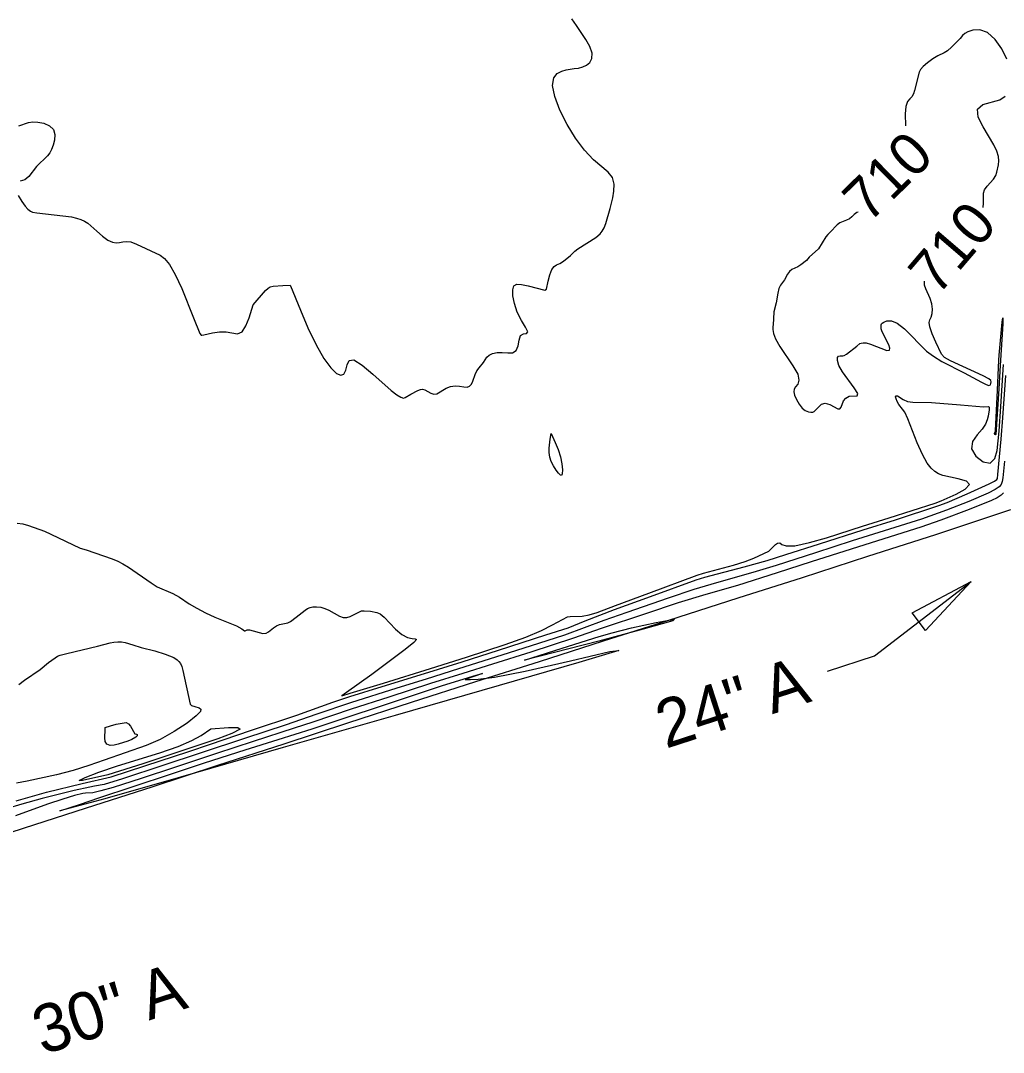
# Model space of a CAD drawing. Extents: x -468541894 to 3393103, y -306086142 to 1227927.
# Drawn here: x 1845028 to 1845797, y 538378 to 539185 of the extents above; entities that cross this region are included whole.
import ezdxf

# ---------------------------------------------------------------- set-up
doc = ezdxf.new("R2010")
doc.units = 0
for name, color, linetype in [('DT_X_Contour_Minor', 7, 'Continuous'), ('Level 14', 7, 'Continuous'), ('Level 19', 7, 'Continuous'), ('Level 40', 7, 'Continuous')]:
    doc.layers.add(name, color=color, linetype=linetype)

msp = doc.modelspace()

# ---------------------------------------------------------------- linework, layer by layer
at = {"layer": 'DT_X_Contour_Minor'}
for points in [[(1845461.01, 539147.19), (1845464.33, 539147.67), (1845467.64, 539148.5), (1845470.72, 539149.91), (1845473.29, 539152.12), (1845474.88, 539155.24), (1845474.95, 539159.36), (1845473.17, 539164.47), (1845470.1, 539170.1), (1845462.86, 539180.84), (1845459.23, 539186.18)], [(1845799.27, 539154.71), (1845795.43, 539162.73), (1845790.16, 539170.1), (1845784.17, 539175.34), (1845778.14, 539177.45), (1845772.75, 539177.26), (1845768.67, 539176.01), (1845766.27, 539174.69), (1845764.7, 539173.11), (1845762.8, 539170.81), (1845759.74, 539167.56), (1845756.08, 539164.04), (1845752.72, 539161.16), (1845750.24, 539159.55), (1845745.32, 539157.19), (1845741.46, 539154.78), (1845737.24, 539151.76), (1845733.72, 539148.84), (1845731.69, 539146.51), (1845730.76, 539144.48), (1845727.11, 539130.02), (1845726.27, 539127.39), (1845725.09, 539125.28), (1845723.41, 539123.59), (1845721.65, 539121.42), (1845720.32, 539117.68), (1845719.8, 539111.75), (1845720.04, 539102.53)], [(1845238.97, 538977.85), (1845239.1, 538977.53), (1845246.91, 538958.27), (1845252.79, 538944.59), (1845259.15, 538931.22), (1845265.21, 538920.66), (1845270.62, 538913.3), (1845275.12, 538908.97), (1845278.55, 538907.49), (1845280.95, 538908.45), (1845282.46, 538911.4), (1845283.4, 538915.59), (1845284.99, 538919.04), (1845288.66, 538919.43), (1845295.26, 538915.27), (1845303.51, 538908.31), (1845317.86, 538895.6), (1845322.41, 538892.1), (1845325.49, 538890.24), (1845327.46, 538889.71), (1845328.97, 538890.18), (1845333.22, 538892.8), (1845338.75, 538895.63), (1845340.79, 538896.44), (1845342.49, 538896.63), (1845344.29, 538896.09), (1845348.99, 538893.47), (1845351.38, 538892.68), (1845353.51, 538893), (1845361.01, 538897.38), (1845364.42, 538898.64), (1845367.99, 538899.24), (1845371.45, 538899.01), (1845374.59, 538898.47), (1845377.23, 538898.3), (1845379.21, 538899.03), (1845380.66, 538900.61), (1845381.75, 538902.81), (1845383.68, 538908.2), (1845384.94, 538910.88), (1845386.6, 538913.25), (1845390.06, 538917.49), (1845392.63, 538921.56), (1845394.44, 538923.25), (1845397.15, 538924.5), (1845400.66, 538925.22), (1845404.71, 538925.35), (1845408.99, 538925.04), (1845412.88, 538925.15), (1845415.73, 538926.75), (1845417.14, 538930.46), (1845417.9, 538934.95), (1845419.1, 538938.45), (1845421.41, 538939.78), (1845423.75, 538940.17), (1845424.62, 538941.44), (1845423, 538945), (1845419.83, 538950.42), (1845416.53, 538956.87), (1845414.25, 538963.52), (1845413.13, 538969.6), (1845413.03, 538974.4), (1845413.92, 538977.36), (1845416.04, 538978.63), (1845419.73, 538978.57), (1845425.03, 538977.53), (1845438.13, 538974.09), (1845439.27, 538974.68), (1845440.77, 538981.16), (1845442.02, 538986.08), (1845443.54, 538990.24), (1845445.27, 538992.58), (1845447.28, 538993.75), (1845449.7, 538994.82), (1845452.55, 538996.59), (1845458, 539001.09), (1845461.6, 539004.62), (1845463.82, 539006.3), (1845477.97, 539015.13), (1845481.19, 539018.11), (1845482.89, 539020.08), (1845484.47, 539022.7), (1845485.81, 539026.1), (1845489.05, 539037.74), (1845491.13, 539046.08), (1845492.06, 539051.34), (1845492.23, 539056.88), (1845490.89, 539061.98), (1845487.5, 539066.21), (1845476.06, 539075.95), (1845469.1, 539083.53), (1845462.03, 539092.94), (1845455.4, 539103.6), (1845449.76, 539114.81), (1845445.77, 539125.39), (1845444.06, 539134.07), (1845445.02, 539139.9), (1845447.81, 539143.35), (1845451.33, 539145.23), (1845454.68, 539146.26), (1845461.01, 539147.19)], [(1845780.63, 539038.55), (1845781, 539042.01), (1845781.06, 539049.74), (1845781.83, 539052.58), (1845783.83, 539055.35), (1845788.92, 539060.89), (1845790.52, 539063.64), (1845791.44, 539066.39), (1845792.67, 539072.01), (1845792.99, 539075.1), (1845792.66, 539078.58), (1845791.37, 539082.67), (1845788.95, 539087.7), (1845780.63, 539101.66), (1845776.9, 539109.37), (1845776.35, 539115.55), (1845780.41, 539119.13), (1845793.71, 539122.88), (1845797.96, 539125.72)], [(1845026.88, 539102.59), (1845034.31, 539105.12), (1845037.76, 539105.65), (1845041.66, 539105.48), (1845046.25, 539104.46), (1845050.68, 539102.5), (1845053.86, 539099.53), (1845055.02, 539095.62), (1845054.64, 539091.32), (1845053.55, 539087.31), (1845052.39, 539084.09), (1845051.04, 539081.49), (1845049.2, 539079.16), (1845040.57, 539070.72), (1845034.61, 539062.95), (1845031.38, 539060.23), (1845027.86, 539059.15)], [(1845026.32, 539048.13), (1845029.14, 539043.26), (1845031.73, 539039.64), (1845033.96, 539037.27), (1845035.88, 539035.86), (1845037.56, 539035.11), (1845040.98, 539034.58), (1845067.94, 539031.34), (1845071.98, 539030.37), (1845075.38, 539029.27), (1845078.17, 539028.01), (1845080.81, 539026.28), (1845087.84, 539020.14), (1845092.22, 539016.32), (1845096.43, 539013.19), (1845099.99, 539011.48), (1845102.98, 539010.97), (1845105.61, 539011.23), (1845108.12, 539011.8), (1845110.9, 539012.13), (1845114.37, 539011.67), (1845118.76, 539010.08), (1845137.3, 539001.43), (1845140.6, 538998.73), (1845144.48, 538994.03), (1845149.03, 538986.31), (1845154.19, 538975.23), (1845163.4, 538952.51)], [(1845683.02, 539035.08), (1845682.08, 539034.75), (1845679.94, 539033.16), (1845678.15, 539031.33), (1845676.22, 539029.74), (1845673.82, 539028.67), (1845671.16, 539027.82), (1845668.63, 539026.73), (1845666.48, 539025.06), (1845661.06, 539019.32), (1845659.28, 539017.65), (1845657.64, 539015.7), (1845651.92, 539006.3), (1845644.82, 538999.69), (1845642.55, 538997.24)], [(1845642.55, 538997.24), (1845638.1, 538993.77), (1845635.84, 538992.38), (1845631.2, 538990.07), (1845629.26, 538988.6), (1845627.79, 538986.57), (1845625.34, 538982), (1845622.39, 538978.03), (1845621.1, 538975.37), (1845620.18, 538971.75), (1845618.89, 538964.1), (1845616.95, 538957.04), (1845616.78, 538951.56), (1845616.52, 538947.15), (1845616.29, 538945.43), (1845616.3, 538943.31), (1845616.87, 538940.25), (1845618.48, 538935.92), (1845621.71, 538930.08), (1845631.99, 538914.97), (1845635.77, 538908.25), (1845636.73, 538903.6), (1845635.71, 538900.61), (1845634.1, 538898.52), (1845633.04, 538896.63), (1845632.79, 538894.52), (1845633.36, 538891.85), (1845634.75, 538888.43), (1845636.76, 538884.83), (1845639.14, 538881.78), (1845641.66, 538879.84), (1845644.06, 538878.85), (1845646.06, 538878.51), (1845647.52, 538878.57), (1845648.72, 538879.18), (1845654.24, 538884.84), (1845657.23, 538885.73), (1845660.74, 538884.72), (1845667.07, 538881.27), (1845668.76, 538881.29), (1845669.7, 538882.65), (1845671.6, 538887.41), (1845673.35, 538889.69), (1845675.96, 538891.06), (1845682.14, 538891.43), (1845682.7, 538893.25), (1845679.97, 538897.74), (1845670.81, 538910.13), (1845667.99, 538915.21), (1845666.81, 538918.9), (1845666.84, 538921.25), (1845667.64, 538922.39), (1845668.82, 538922.7), (1845671.03, 538922.61), (1845672.16, 538922.98), (1845673.88, 538924.05), (1845681.88, 538930.34), (1845684.42, 538932.27), (1845685.41, 538932.63), (1845686.92, 538932.88), (1845689.26, 538932.75), (1845692.66, 538931.86), (1845705.51, 538926.8), (1845707.46, 538927.06), (1845707.8, 538928.69), (1845706.94, 538931.35), (1845701.86, 538941.37), (1845701.04, 538943.86), (1845700.92, 538946.9), (1845701.15, 538947.69), (1845701.76, 538948.31), (1845703.11, 538949.05), (1845705.49, 538949.96), (1845708.97, 538950.09), (1845713.54, 538948.25), (1845719.1, 538943.71), (1845736.32, 538926.44), (1845741.83, 538922.3), (1845748.51, 538918.26), (1845765.86, 538909.29), (1845779.48, 538902.16), (1845783.11, 538900.19), (1845785.23, 538899.45), (1845786.35, 538899.92), (1845786.83, 538901.11), (1845786.95, 538902.42), (1845786.74, 538903.46), (1845785.1, 538904.75), (1845780.62, 538907.01), (1845755.08, 538918.77), (1845750.39, 538921.49), (1845748.05, 538924.02), (1845743.72, 538933.34), (1845740.95, 538939.77), (1845738.96, 538945.3), (1845738.49, 538948.76), (1845739.11, 538950.86), (1845740.13, 538952.84), (1845740.94, 538955.65), (1845741.2, 538959.25), (1845740.67, 538963.32)], [(1845740.67, 538963.32), (1845739.25, 538967.55), (1845735.84, 538975.18), (1845734.99, 538977.98), (1845734.85, 538981.04)], [(1845163.4, 538952.51), (1845168.42, 538940.03), (1845169.41, 538938.85), (1845169.98, 538938.71), (1845171.51, 538939.01), (1845178.25, 538940.58), (1845183.58, 538941.41), (1845189.03, 538941.48), (1845197.88, 538939.93), (1845201.39, 538941.43), (1845204.41, 538946.1), (1845206.87, 538952.35), (1845209.98, 538962.44), (1845219.76, 538973.8), (1845221.65, 538975.69), (1845223.36, 538976.65), (1845225.71, 538977.12), (1845233.13, 538977.62), (1845238.97, 538977.85)], [(1845790.42, 538864.02), (1845792.04, 538895.92), (1845793.02, 538919.23), (1845793.22, 538923.21), (1845795.69, 538948.97), (1845796.19, 538952.47), (1845796.06, 538947.59), (1845794.09, 538915.06), (1845792.95, 538896.87), (1845790.61, 538861.15), (1845790.41, 538860.94), (1845789.78, 538861.25), (1845789.66, 538861.93), (1845790.35, 538863.31), (1845790.42, 538864.02)], [(1845312.41, 538718.33), (1845321.34, 538708.99), (1845326.17, 538704.83), (1845330.6, 538702.58), (1845334.24, 538701.76), (1845336.78, 538701.49), (1845337.65, 538700.81), (1845335.5, 538698.45), (1845328.77, 538693.06), (1845302.68, 538673.56), (1845282.99, 538659.36), (1845279.46, 538656.85), (1845285.72, 538658.87), (1845311.81, 538666.89), (1845348.58, 538678.19), (1845376.75, 538687.01), (1845407.1, 538697), (1845423.11, 538702.82), (1845435.47, 538708.05), (1845444.14, 538712.32), (1845455.8, 538718.55), (1845457.87, 538718.94), (1845467.29, 538719.24), (1845472.64, 538720.19), (1845478.83, 538722.03), (1845493.31, 538727.61), (1845519.35, 538737.21), (1845557.19, 538751.1), (1845562.02, 538752.67), (1845585.44, 538759.05), (1845594.67, 538761.9), (1845601.35, 538764.42), (1845613.23, 538770.06), (1845618.26, 538775.22), (1845620.03, 538776.32), (1845621.72, 538776.44), (1845623.42, 538775.3), (1845626.71, 538774.05), (1845633.55, 538774.17), (1845644.94, 538776.65), (1845658.17, 538780.46), (1845686.37, 538789.41), (1845707.18, 538796), (1845743.08, 538807.48), (1845747.78, 538809.21), (1845759.7, 538814.55), (1845766.71, 538818.45), (1845770.15, 538822.08), (1845767.65, 538824.75), (1845761.31, 538826.59), (1845749.23, 538829.15), (1845745.76, 538830.49), (1845742.97, 538832.24), (1845740.07, 538834.78), (1845736.83, 538838.89), (1845733.18, 538845.45), (1845729.16, 538854.78), (1845721.8, 538873.48), (1845719.37, 538878.55), (1845717.65, 538881.09), (1845714.8, 538884.68), (1845713.51, 538886.93), (1845712.59, 538889.04), (1845712.27, 538890.64), (1845712.61, 538891.48), (1845713.67, 538891.32), (1845718.08, 538888.43), (1845721.49, 538887.04), (1845725.87, 538886.47), (1845740.32, 538886.12), (1845763.1, 538884.3), (1845781.02, 538882.8), (1845784.94, 538883.07), (1845785.32, 538882.51), (1845785.31, 538880.49), (1845784.56, 538875.4), (1845783.89, 538872.66), (1845782.5, 538869.31), (1845779.88, 538865.36), (1845775.96, 538860.83), (1845772.51, 538855.74), (1845771.73, 538850.07), (1845775.04, 538844.16), (1845780.74, 538839.69), (1845786.33, 538838.7), (1845789.88, 538842.38), (1845791.62, 538848.77), (1845793.16, 538863.81), (1845794.45, 538883.1), (1845796.73, 538915.99)], [(1845076.24, 538588.26), (1845099.08, 538593.58), (1845125.21, 538602.12), (1845159.65, 538613.44), (1845176.72, 538619.15), (1845207.86, 538629.66), (1845244.15, 538641.88), (1845272.35, 538651.81), (1845285.71, 538656.32), (1845310.94, 538664.15), (1845343.94, 538674.33), (1845373.34, 538683.56), (1845401.9, 538692.64), (1845438.92, 538704.46), (1845456.21, 538710.14), (1845469.59, 538715.39), (1845492.61, 538724.46), (1845520.65, 538734.57), (1845556.38, 538747.45), (1845563.02, 538749.52), (1845593.8, 538757.76), (1845611.97, 538762.71), (1845626.46, 538767.24), (1845652.67, 538775.65), (1845686.83, 538786.57), (1845712.15, 538794.56), (1845746.15, 538805.64), (1845752.55, 538808.06), (1845768.17, 538814.8), (1845785.32, 538822.59), (1845789.71, 538824.77), (1845791.47, 538825.93), (1845791.88, 538826.71), (1845792.29, 538829.88), (1845794.74, 538857.57), (1845796.22, 538874.31), (1845798.48, 538907.39)], [(1845442.9, 538862.08), (1845446.19, 538854.81), (1845448.36, 538849.45), (1845450.26, 538843.66), (1845451.39, 538838.22), (1845451.8, 538833.68), (1845451.67, 538830.54), (1845451.14, 538829.16), (1845450.19, 538829.37), (1845448.76, 538830.89), (1845446.86, 538833.41), (1845444.84, 538836.59), (1845443.12, 538840.06), (1845442.03, 538843.54), (1845441.52, 538847.02), (1845441.48, 538850.6), (1845442.19, 538857.59), (1845442.9, 538862.08)], [(1845797.49, 538840.44), (1845796.14, 538827.41), (1845795.61, 538824.41), (1845794.84, 538822.16), (1845793.22, 538820.23), (1845790, 538818.11), (1845784.67, 538815.39), (1845769.65, 538808.78), (1845752.19, 538801.91), (1845732.43, 538795.02), (1845703.25, 538785.75), (1845678.36, 538777.92), (1845649.53, 538768.66), (1845618.91, 538758.8), (1845600.75, 538753.2), (1845572.26, 538745.32), (1845554.57, 538740.11), (1845534.46, 538733.28), (1845502.05, 538721.91), (1845484.15, 538715.79), (1845453.31, 538704.36), (1845433.04, 538697.76), (1845404.48, 538688.65), (1845370.64, 538678.03), (1845345.21, 538669.96), (1845322.28, 538662.75), (1845286.19, 538651.39), (1845259.9, 538642.46), (1845234.99, 538634.03), (1845204.01, 538623.9)], [(1845796.73, 538815.7), (1845794.68, 538813.63), (1845791.76, 538811.76), (1845787.17, 538809.6), (1845769.77, 538802.63), (1845747.52, 538794.16), (1845732.05, 538788.79), (1845702.96, 538779.72), (1845677.41, 538771.66), (1845646.38, 538761.67), (1845619.57, 538752.99), (1845588.71, 538743.26), (1845563.8, 538736.08), (1845542.41, 538729.54), (1845516.66, 538720.89), (1845482, 538709.5), (1845460.4, 538701.91), (1845427.15, 538691.07), (1845397.07, 538681.54), (1845374.06, 538674.44), (1845348.65, 538666.41), (1845316.09, 538655.95), (1845286.67, 538646.45), (1845256.54, 538636.32), (1845242.18, 538631.54), (1845209.89, 538621.3), (1845181.37, 538611.88), (1845148.39, 538600.95), (1845122.34, 538592.37), (1845100.49, 538585.32), (1845091.01, 538582.56), (1845084.65, 538581.13), (1845078.93, 538580.69), (1845076.77, 538580.56), (1845070.44, 538578.91), (1845061.34, 538576.2), (1845049.11, 538572.12), (1845024.3, 538563.14)], [(1845025.45, 538791.79), (1845029.95, 538791.37), (1845034.32, 538790.14), (1845046.91, 538785.52), (1845051.91, 538783.35), (1845074.71, 538772.39), (1845079.33, 538770.96), (1845099.87, 538763.86), (1845104.25, 538762.09), (1845108.08, 538760.14), (1845112.61, 538757.34), (1845130.18, 538745.31), (1845135, 538742.15), (1845147.22, 538736.9), (1845152.37, 538733.94), (1845160.09, 538728.87), (1845165.96, 538725.35), (1845172.78, 538721.74), (1845180.12, 538718.45), (1845196.99, 538711.54), (1845201.06, 538709.18), (1845203.19, 538707.73), (1845203.86, 538707.6), (1845205.28, 538708.42), (1845207.14, 538708.38), (1845217.61, 538705.62), (1845220.1, 538705.92), (1845221.92, 538707.03), (1845225.8, 538710.13), (1845228.21, 538711.52), (1845230.65, 538712.52), (1845237.18, 538713.88), (1845239.26, 538714.98), (1845243.63, 538718.4), (1845250.56, 538723.84), (1845252.5, 538725.11), (1845254.45, 538725.99), (1845256.76, 538726.47), (1845259.65, 538726.53), (1845262.9, 538726.15), (1845266.17, 538725.26), (1845269.21, 538723.86), (1845277.6, 538719.11), (1845280.41, 538718.24), (1845283.2, 538718.14), (1845285.94, 538718.95), (1845294.66, 538723.2), (1845296.69, 538723.4), (1845301.66, 538722.97), (1845306.61, 538722.08), (1845309.19, 538720.91), (1845312.41, 538718.33)], [(1845422.22, 538684.68), (1845451.49, 538694.08), (1845480.42, 538703.34), (1845490.69, 538706.21), (1845505.87, 538709.94), (1845524.99, 538714.11), (1845539.3, 538716.74), (1845538.13, 538715.47), (1845514.99, 538708.93), (1845480.15, 538699.71), (1845422.22, 538684.68)], [(1845026.75, 538665.74), (1845031.17, 538669.11), (1845043.6, 538677.38), (1845049.99, 538682.87), (1845055.11, 538686.61), (1845057.11, 538687.77), (1845059, 538688.56), (1845064.26, 538689.96), (1845088.32, 538695.65), (1845098.19, 538698.41), (1845101.18, 538698.9), (1845104.2, 538699.12), (1845107.07, 538698.97), (1845109.87, 538698.46), (1845115.91, 538696.66), (1845122.54, 538694.59), (1845133.06, 538692.11), (1845141.09, 538689.44), (1845148.01, 538686.72), (1845150.53, 538685.08), (1845151.9, 538683.78), (1845153.15, 538682.09), (1845154.15, 538679.88), (1845155.05, 538676.7), (1845160.81, 538650.49), (1845161.72, 538649.25), (1845164.35, 538648.54), (1845167.84, 538647.46), (1845169.17, 538646.57), (1845168.87, 538644.75), (1845165.55, 538641.24), (1845158.31, 538635.62), (1845148.32, 538628.97), (1845137.25, 538622.74), (1845126.42, 538617.98), (1845093.59, 538606.69), (1845081.66, 538602.48), (1845069.16, 538598.51), (1845056.3, 538595.12), (1845033.45, 538590.25), (1845025.11, 538588.59)], [(1845375.88, 538669.74), (1845379.86, 538669.64), (1845385.87, 538669.78), (1845398.74, 538671.42), (1845422.71, 538676.12), (1845458, 538684.26), (1845488.97, 538691.53), (1845495.99, 538692.42), (1845464.75, 538682.91), (1845402.31, 538664.85), (1845321.04, 538641.55), (1845233.53, 538616.44), (1845153.25, 538593.4), (1845093.92, 538576.45), (1845058.81, 538566.86), (1845074.21, 538572.01), (1845090.16, 538577.37), (1845115.32, 538585.65), (1845146.99, 538596.1), (1845172.09, 538604.41), (1845203.72, 538614.71), (1845229.5, 538622.73), (1845256.11, 538631.15), (1845275.69, 538637.65), (1845317.41, 538651.49), (1845357.97, 538664.85), (1845384.33, 538672.95), (1845389.26, 538674.22), (1845375.88, 538669.74)], [(1845176.96, 538631.11), (1845190.82, 538632.15), (1845197.9, 538632.16), (1845199.8, 538630.77), (1845193.46, 538627.5), (1845182.38, 538623.33), (1845151.89, 538613.08), (1845123.67, 538603.81), (1845096.51, 538595.03), (1845076.68, 538590.66), (1845074.1, 538590.73), (1845078.65, 538593.09), (1845089.26, 538597.2), (1845103.89, 538602.19), (1845136.99, 538612.37), (1845151.39, 538617.29), (1845162.1, 538621.93), (1845169.32, 538625.93), (1845176.96, 538631.11)], [(1845094.35, 538632.06), (1845098.54, 538633.54), (1845102.85, 538634.61), (1845110.78, 538635.96), (1845112.45, 538635.1), (1845114.04, 538633.06), (1845117.55, 538627.21), (1845118.72, 538626.79), (1845119.2, 538626.61), (1845119.45, 538626.2), (1845119.2, 538625.53), (1845118.28, 538624.63), (1845115.27, 538622.72), (1845112.15, 538621.49), (1845104.4, 538619.01), (1845101.32, 538618.34), (1845098.2, 538618.16), (1845095.73, 538618.97), (1845094.41, 538621.09), (1845093.99, 538623.95), (1845094.22, 538630.46), (1845094.35, 538632.06)], [(1845204.01, 538623.9), (1845168.66, 538612.05), (1845139.29, 538602.35), (1845107.92, 538592.04), (1845093.56, 538587.63), (1845086.04, 538586.17), (1845082.25, 538585.57), (1845070.04, 538582.85), (1845045.16, 538576.57), (1845029.05, 538572.19), (1845004.42, 538564.9)], [(1845024.66, 538574.8), (1845048.47, 538581.52), (1845076.24, 538588.26)]]:
    msp.add_lwpolyline(points, dxfattribs=at)
at = {"layer": 'Level 14'}
msp.add_lwpolyline([(1845802.17, 538802.16), (1845743.35, 538782.86), (1845690.35, 538765.74), (1845639.28, 538749.23), (1845588.9, 538733.21), (1845534.6, 538715.88), (1845483.66, 538699.59), (1845433.62, 538683.58), (1845383.72, 538667.75), (1845333.52, 538651.64), (1845283.77, 538635.54), (1845234.02, 538619.22), (1845182.03, 538602.29), (1845130.73, 538585.56), (1845079.55, 538568.99), (1845030.09, 538553.29), (1844978.48, 538536.6), (1844929.9, 538520.7), (1844871.29, 538501.95), (1844825.72, 538486.64), (1844773.74, 538469.67), (1844725.53, 538454.22), (1844675.81, 538437.82), (1844623.12, 538421.09)], dxfattribs=at)
at = {"layer": 'Level 40'}
for p, q in [((1845725.14, 538721.68), (1845771.23, 538746.37)), ((1845771.23, 538746.37), (1845735.63, 538708.08)), ((1845735.63, 538708.08), (1845725.14, 538721.68))]:
    msp.add_line(p, q, dxfattribs=at)
msp.add_lwpolyline([(1845658.91, 538676.19), (1845695.76, 538688.15), (1845771.23, 538746.37)], dxfattribs=at)

# ---------------------------------------------------------------- texts
at = {"layer": 'Level 19'}
for rotation, p in [(44.50631, (1845691.16, 539025.61)), (49.43547, (1845745.03, 538968.77))]:
    msp.add_text('710', height=33, rotation=rotation, dxfattribs=at).set_placement(p)
at = {"layer": 'Level 40'}
for s, p in [('24" A', (1845532.56, 538615.38)), ('30" A', (1845045.32, 538375.96))]:
    msp.add_text(s, height=37.5, rotation=17.9864, dxfattribs=at).set_placement(p)

doc.saveas('drawing.dxf')
